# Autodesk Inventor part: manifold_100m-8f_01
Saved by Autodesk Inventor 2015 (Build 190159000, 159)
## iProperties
Created: 2021-02
Part Number: manifold_100m-8f_01
Checked By: TraceParts S.A.
Material: Generic
Catalog Web Link: www.traceparts.com
Document SubType Name: Modeling
Designer: TraceParts
Density: 1 g/cm^3
Appearance: Default
Company: TraceParts S.A.
Author: TraceParts
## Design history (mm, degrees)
feature "manifold_100m-8f_01.ipt"
body "Solid1"
